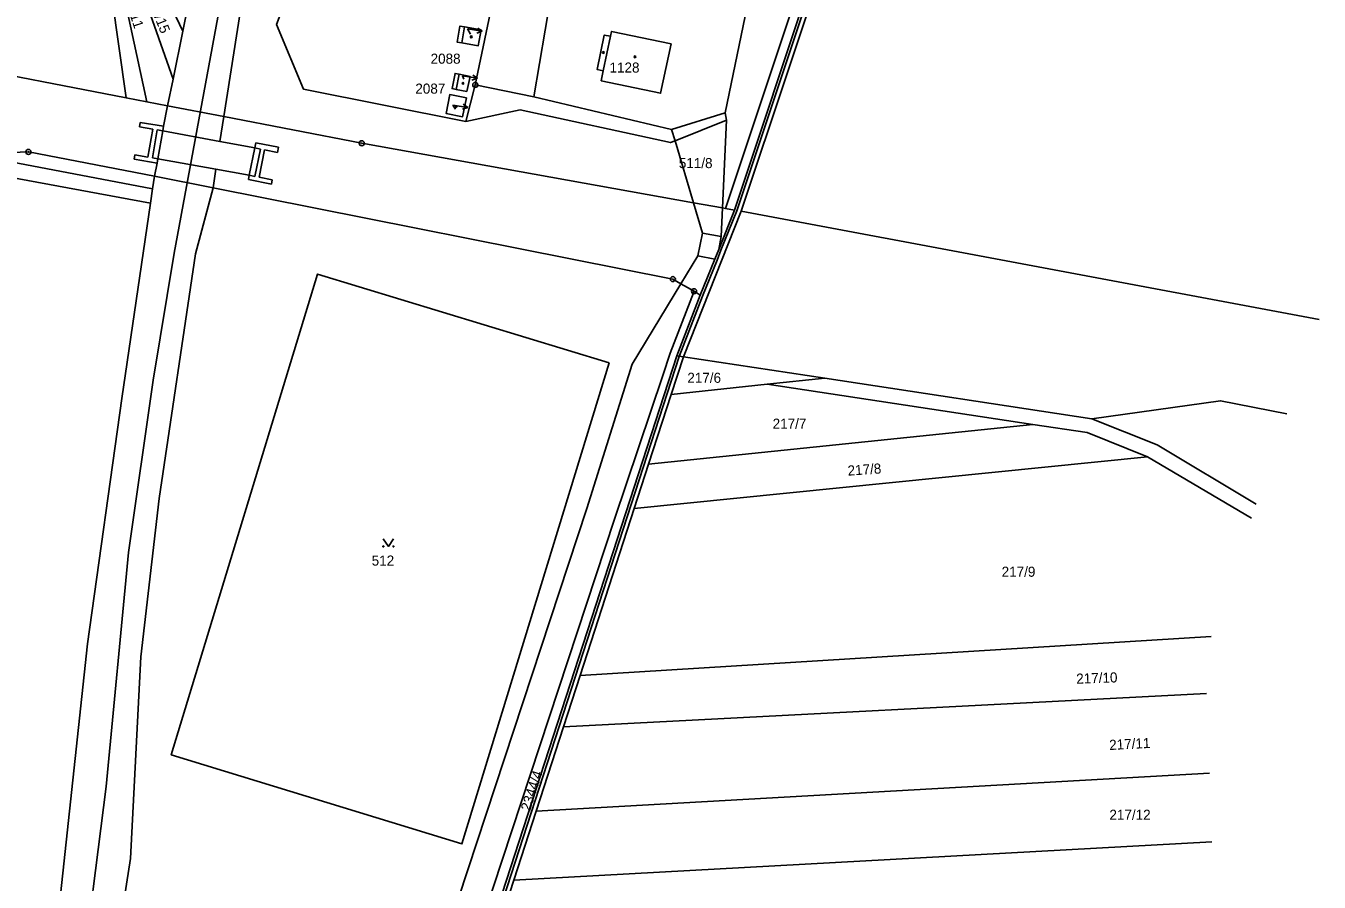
# Model space of a CAD drawing. Extents: x -555757 to -553364, y -1100723 to -1096439.
# Drawn here: x -553994.7 to -553738.1, y -1100289.4 to -1100119.7 of the extents above; entities that cross this region are included whole.
import ezdxf

# ---------------------------------------------------------------- set-up
doc = ezdxf.new("R2010")
doc.units = 0
for name, color, linetype in [('01_HLADINA', 7, 'Continuous'), ('BUDOVY', 7, 'Continuous'), ('C$SLO$PARCELY', 7, 'Continuous'), ('HRANICE$PARCELY', 7, 'Continuous'), ('HRANICE_PARCEL', 7, 'Continuous'), ('PLOTY', 7, 'Continuous'), ('SLOUPY', 7, 'Continuous'), ('SLUCKOV$$C$RA', 7, 'Continuous'), ('VSTUP', 7, 'Continuous'), ('ZNA$KY$KULTUR', 7, 'Continuous')]:
    doc.layers.add(name, color=color, linetype=linetype)

# ---------------------------------------------------------------- blocks, each defined once
blk = doc.blocks.new('4$02')
at = {"layer": 'SLOUPY'}
blk.add_circle((0, 0), 0.175, dxfattribs=at)
blk = doc.blocks.new('1029')
at = {"layer": 'PLOTY'}
for p, q in [((0, 0), (2.964, -0.468)), ((2.964, -0.468), (2.052, 0.182)), ((2.964, -0.468), (1.897, -0.807))]:
    blk.add_line(p, q, dxfattribs=at)
blk = doc.blocks.new('3$14')
at = {"layer": 'ZNA$KY$KULTUR'}
blk.add_lwpolyline([(-1, 1.5), (0, 0), (1, 1.5)], dxfattribs=at)
for centre in [(-1, 0), (1, 0)]:
    blk.add_circle(centre, 0.1, dxfattribs=at)
blk = doc.blocks.new('1$05')
at = {"layer": 'SLOUPY'}
for radius in [0.5, 0.032]:
    blk.add_circle((0, 0), radius, dxfattribs=at)

msp = doc.modelspace()

# ---------------------------------------------------------------- linework, layer by layer
at = {"layer": '01_HLADINA'}
msp.add_lwpolyline([(-553953.11, -1100099.32), (-553965.26, -1100164.74), (-553969.41, -1100189.9), (-553974.3, -1100224.07), (-553978.76, -1100270.49), (-553983.95, -1100311.58), (-553989.5, -1100329.15), (-553995.79, -1100344.5), (-554001.62, -1100365.99), (-554010.25, -1100383.72), (-554044.69, -1100426.79), (-554056.93, -1100450.05), (-554073.88, -1100483.25), (-554097.67, -1100514.34), (-554108.96, -1100533.61), (-554110.14, -1100539.01), (-554109.2, -1100543.24), (-554088.7, -1100559.12), (-554040.77, -1100604.47), (-554031.29, -1100609.85)], dxfattribs=at)
at = {"layer": 'HRANICE$PARCELY'}
for p, q in [((-553974.78, -1100133.9), (-553980.8, -1100091.31)), ((-553973.75, -1100099.21), (-553963.53, -1100120.74)), ((-553976.01, -1100110.13), (-553970.66, -1100134.7)), ((-553965.47, -1100130.22), (-553972.7, -1100109.51)), ((-553963.53, -1100120.74), (-553962.46, -1100115.49)), ((-553963.53, -1100120.74), (-553965.47, -1100130.22)), ((-553966.55, -1100135.49), (-553965.47, -1100130.22)), ((-553974.78, -1100133.9), (-553970.66, -1100134.7)), ((-553970.66, -1100134.7), (-553966.55, -1100135.49)), ((-553966.55, -1100135.49), (-553955.39, -1100137.65)), ((-553865.86, -1100142.45), (-553855.64, -1100138.34)), ((-553855.64, -1100138.34), (-553856.45, -1100155.76)), ((-553862.18, -1100154.74), (-553865.86, -1100142.45)), ((-553957.49, -1100151.77), (-553969.15, -1100149.45)), ((-553862.18, -1100154.74), (-553856.45, -1100155.76)), ((-553864.19, -1100185.27), (-553852.74, -1100156.42)), ((-553856.45, -1100155.76), (-553855.82, -1100155.88)), ((-553855.82, -1100155.88), (-553854.07, -1100156.19)), ((-553738.06, -1100177.87), (-553852.74, -1100156.42)), ((-553874.39, -1100186.73), (-553864.69, -1100170.78)), ((-553862.09, -1100172.27), (-553864.69, -1100170.78)), ((-553860.87, -1100173.08), (-553862.09, -1100172.27)), ((-553866.61, -1100192.72), (-553864.19, -1100185.27)), ((-553864.19, -1100185.27), (-553865.48, -1100185.07)), ((-553864.19, -1100185.27), (-553836.12, -1100189.52)), ((-553866.61, -1100192.72), (-553847.56, -1100190.72)), ((-553836.12, -1100189.52), (-553847.56, -1100190.72)), ((-553847.56, -1100190.72), (-553794.86, -1100198.68)), ((-553836.12, -1100189.52), (-553783.13, -1100197.54)), ((-553871.11, -1100206.59), (-553866.61, -1100192.72)), ((-553871.11, -1100206.59), (-553794.86, -1100198.68)), ((-553873.96, -1100215.36), (-553772.14, -1100205.09)), ((-553772.14, -1100205.09), (-553751.49, -1100217.26)), ((-553873.96, -1100215.36), (-553871.11, -1100206.59)), ((-553884.7, -1100248.44), (-553873.96, -1100215.36)), ((-553884.7, -1100248.44), (-553759.5, -1100240.75)), ((-553888, -1100258.61), (-553884.7, -1100248.44)), ((-553888, -1100258.61), (-553760.38, -1100252.01)), ((-553893.42, -1100275.33), (-553888, -1100258.61)), ((-553893.42, -1100275.33), (-553759.84, -1100267.83)), ((-553897.87, -1100289.02), (-553893.42, -1100275.33)), ((-553897.87, -1100289.02), (-553759.37, -1100281.41))]:
    msp.add_line(p, q, dxfattribs=at)
for points in [[(-553907.37, -1100138.61), (-553939.55, -1100132.22), (-553944.91, -1100119.39), (-553920.27, -1100053.8), (-553914.93, -1100045.6), (-553847.15, -1099965.99), (-553812.36, -1099934.8), (-553809.19, -1099892.09), (-553807.54, -1099892.27), (-553806.84, -1099889.23), (-553809.31, -1099888.44), (-553798.08, -1099842.22), (-553794.08, -1099832.41)], [(-553852.74, -1100156.42), (-553750.94, -1099851.94), (-553751.35, -1099851.71)], [(-553820.44, -1099888.78), (-553821.21, -1099891.71), (-553820.09, -1099892.13), (-553820.37, -1099892.88), (-553821.49, -1099892.46), (-553824.11, -1099899.49), (-553822.99, -1099899.91), (-553823.26, -1099900.66), (-553824.39, -1099900.24), (-553825.18, -1099904.09), (-553825.84, -1099907.27), (-553822.76, -1099907.91), (-553822.92, -1099908.7), (-553817.67, -1099909.79), (-553816.58, -1099926.52), (-553821.03, -1099933.32), (-553832.46, -1099946.01), (-553847.23, -1099954.8), (-553908.3, -1100026.68), (-553927.2, -1100052.65), (-553950.17, -1100104.31), (-553955.39, -1100137.65)], [(-553827.74, -1100062.31), (-553830.25, -1100061.66), (-553887.72, -1100046.78), (-553905.49, -1100131.36), (-553907.37, -1100138.61)], [(-553855.82, -1100155.88), (-553824.86, -1100063.06), (-553825.46, -1100062.9)], [(-554085.02, -1100114.21), (-554082.54, -1100114.55), (-554010.35, -1100127.02), (-553974.78, -1100133.9)], [(-553904.36, -1100120.43), (-553907.61, -1100119.87), (-553908.55, -1100119.71), (-553909.1, -1100122.86), (-553908.16, -1100123.02), (-553904.91, -1100123.59), (-553904.36, -1100120.43)], [(-553878.66, -1100121.73), (-553879.9, -1100121.47), (-553881.31, -1100128.33), (-553880.09, -1100128.58), (-553880.5, -1100130.54), (-553868.73, -1100133.02), (-553866.66, -1100123.24), (-553878.45, -1100120.76), (-553878.66, -1100121.73)], [(-553907.14, -1100132.67), (-553906.54, -1100129.68), (-553908.7, -1100129.25), (-553909.5, -1100129.09), (-553910.09, -1100132.09), (-553909.3, -1100132.24), (-553907.14, -1100132.67)], [(-553907.27, -1100133.93), (-553910.55, -1100133.28), (-553911.3, -1100137.03), (-553908.01, -1100137.68), (-553907.27, -1100133.93)], [(-553865.86, -1100142.45), (-553866.76, -1100142.81), (-553896.58, -1100136.32), (-553907.37, -1100138.61)], [(-553955.39, -1100137.65), (-553928.03, -1100142.94), (-553862.18, -1100154.74)], [(-553969.15, -1100149.45), (-553994.16, -1100144.65), (-554005.7, -1100145.07), (-554026.82, -1100141.05)], [(-553975.6, -1100193.57), (-553969.94, -1100154.83), (-553969.52, -1100151.97), (-553969.15, -1100149.45)], [(-553957.49, -1100151.77), (-553961.04, -1100164.84), (-553968.24, -1100213.36), (-553971.85, -1100244.73), (-553973.89, -1100284.73), (-553980.03, -1100324.22), (-553990.03, -1100341.67), (-553995.55, -1100364.16), (-554005.15, -1100386.96), (-554032.98, -1100417.03), (-554047.76, -1100443)], [(-553864.69, -1100170.78), (-553866.29, -1100169.87), (-553957.49, -1100151.77)], [(-553878.94, -1100186.47), (-553908.16, -1100281.84), (-553965.81, -1100264.16), (-553936.78, -1100168.87), (-553878.94, -1100186.47)], [(-553868.31, -1100189), (-553866.84, -1100184.54), (-553862.09, -1100172.27)], [(-553936.03, -1100360.91), (-553925.98, -1100343.56), (-553919.7, -1100325.51), (-553883.36, -1100215.37), (-553874.39, -1100186.73)], [(-553903.81, -1100296.11), (-553877.84, -1100217.43), (-553868.31, -1100189)], [(-553990.26, -1100314.68), (-553982.45, -1100242.15), (-553975.6, -1100193.57)], [(-553783.13, -1100197.54), (-553757.61, -1100194), (-553744.44, -1100196.6)], [(-553794.86, -1100198.68), (-553784.06, -1100200.31), (-553772.14, -1100205.09)], [(-553750.55, -1100214.5), (-553770.17, -1100202.71), (-553783.13, -1100197.54)], [(-553899.62, -1100305.56), (-553899.53, -1100303.59), (-553900.98, -1100298.61), (-553897.87, -1100289.02)]]:
    msp.add_lwpolyline(points, dxfattribs=at)
at = {"layer": 'HRANICE_PARCEL'}
msp.add_line((-553860.87, -1100173.08), (-553865.48, -1100185.07), dxfattribs=at)
msp.add_line((-553860.87, -1100173.08), (-553865.48, -1100185.07), dxfattribs=at)
for points in [[(-553772.42, -1099910.5), (-553808.14, -1100018.35), (-553854.07, -1100156.19)], [(-553772.42, -1099910.5), (-553808.14, -1100018.35), (-553854.07, -1100156.19)], [(-553854.07, -1100156.19), (-553857.2, -1100163.97), (-553857.97, -1100165.89), (-553860.87, -1100173.08)], [(-553854.07, -1100156.19), (-553857.2, -1100163.97), (-553857.97, -1100165.89), (-553860.87, -1100173.08)], [(-553865.48, -1100185.07), (-553901.86, -1100296.95), (-553904.98, -1100335.31), (-553898.6, -1100364.02), (-553903.77, -1100393.32)], [(-553865.48, -1100185.07), (-553901.86, -1100296.95), (-553904.98, -1100335.31), (-553898.6, -1100364.02), (-553903.77, -1100393.32)]]:
    msp.add_lwpolyline(points, dxfattribs=at)
at = {"layer": 'PLOTY'}
for p, q in [((-553906.45, -1100121.3), (-553907.07, -1100120.27)), ((-553907.75, -1100130.22), (-553908.05, -1100129.59)), ((-553909.43, -1100136.16), (-553909.96, -1100135.37))]:
    msp.add_line(p, q, dxfattribs=at)
at = {"layer": 'SLUCKOV$$C$RA'}
for p, q in [((-553807.67, -1100018.51), (-553853.6, -1100156.36)), ((-553881.2, -1100059.22), (-553893.89, -1100133.71)), ((-553855.92, -1100136.88), (-553841.85, -1100069.34)), ((-553908.16, -1100123.02), (-553907.61, -1100119.87)), ((-553880.09, -1100128.58), (-553878.66, -1100121.73)), ((-553909.3, -1100132.24), (-553908.7, -1100129.25)), ((-553905.49, -1100131.36), (-553893.89, -1100133.71)), ((-553893.89, -1100133.71), (-553866.54, -1100140.2)), ((-553967.39, -1100139.57), (-553966.55, -1100135.49)), ((-553866.54, -1100140.2), (-553855.92, -1100136.88)), ((-553855.64, -1100138.34), (-553855.92, -1100136.88)), ((-553971.96, -1100138.8), (-553972.11, -1100139.68)), ((-553972.11, -1100139.68), (-553969.48, -1100140.15)), ((-553967.39, -1100139.57), (-553971.96, -1100138.8)), ((-553967.5, -1100140.5), (-553967.39, -1100139.57)), ((-553956.16, -1100142.58), (-553955.39, -1100137.65)), ((-553969.48, -1100140.15), (-553970.44, -1100145.66)), ((-553969.56, -1100145.81), (-553968.59, -1100140.3)), ((-553968.59, -1100140.3), (-553967.5, -1100140.5)), ((-553967.5, -1100140.5), (-553968.47, -1100146)), ((-553956.16, -1100142.58), (-553967.5, -1100140.5)), ((-553866.54, -1100140.2), (-553865.86, -1100142.45)), ((-553969.94, -1100154.83), (-554026.21, -1100144.48)), ((-553949.27, -1100143.85), (-553956.16, -1100142.58)), ((-553950.34, -1100149.29), (-553949.27, -1100143.85)), ((-553949.07, -1100142.82), (-553949.27, -1100143.85)), ((-553949.27, -1100143.85), (-553948.14, -1100144.07)), ((-553948.14, -1100144.07), (-553949.21, -1100149.51)), ((-553944.51, -1100143.71), (-553949.07, -1100142.82)), ((-553948.38, -1100149.67), (-553947.31, -1100144.23)), ((-553947.31, -1100144.23), (-553944.71, -1100144.74)), ((-553944.71, -1100144.74), (-553944.51, -1100143.71)), ((-553969.52, -1100151.97), (-554005.7, -1100145.07)), ((-553973.2, -1100146.1), (-553973.05, -1100145.21)), ((-553968.63, -1100146.88), (-553973.2, -1100146.1)), ((-553973.05, -1100145.21), (-553970.44, -1100145.66)), ((-553969.56, -1100145.81), (-553968.47, -1100146)), ((-553969.15, -1100149.45), (-553968.63, -1100146.88)), ((-553968.47, -1100146), (-553968.63, -1100146.88)), ((-553968.47, -1100146), (-553956.96, -1100148.09)), ((-553957.49, -1100151.77), (-553956.96, -1100148.09)), ((-553956.96, -1100148.09), (-553950.34, -1100149.29)), ((-553950.34, -1100149.29), (-553950.5, -1100150.13)), ((-553949.21, -1100149.51), (-553950.34, -1100149.29)), ((-553945.78, -1100150.18), (-553948.38, -1100149.67)), ((-553950.5, -1100150.13), (-553945.94, -1100151.02)), ((-553945.94, -1100151.02), (-553945.78, -1100150.18)), ((-553860.38, -1100160.76), (-553862.18, -1100154.74)), ((-553853.6, -1100156.36), (-553856.74, -1100164.16)), ((-553856.71, -1100161.44), (-553856.45, -1100155.76)), ((-553861.33, -1100165.26), (-553860.38, -1100160.76)), ((-553860.38, -1100160.76), (-553856.71, -1100161.44)), ((-553857.2, -1100163.97), (-553856.71, -1100161.44)), ((-553864.69, -1100170.78), (-553861.33, -1100165.26)), ((-553861.33, -1100165.26), (-553857.97, -1100165.89)), ((-553856.74, -1100164.16), (-553857.51, -1100166.08)), ((-553857.51, -1100166.08), (-553860.4, -1100173.26)), ((-553860.4, -1100173.26), (-553865.01, -1100185.24)), ((-553865.01, -1100185.24), (-553901.37, -1100297.05))]:
    msp.add_line(p, q, dxfattribs=at)

# ---------------------------------------------------------------- block references
at = {"layer": 'BUDOVY'}
for p in [(-553906.3, -1100121.84), (-553880.09, -1100124.93), (-553873.8, -1100125.79), (-553907.94, -1100131.05), (-553909.32, -1100135.62)]:
    msp.add_blockref('4$02', p, dxfattribs=at)
at = {"layer": 'PLOTY'}
for p in [(-553907.07, -1100120.27), (-553908.05, -1100129.59), (-553909.96, -1100135.37)]:
    msp.add_blockref('1029', p, dxfattribs=at)
at = {"layer": 'VSTUP'}
for p in [(-553905.49, -1100131.36), (-553994.16, -1100144.65), (-553928.03, -1100142.94), (-553866.29, -1100169.87), (-553862.09, -1100172.27)]:
    msp.add_blockref('1$05', p, dxfattribs=at)
at = {"layer": 'ZNA$KY$KULTUR'}
msp.add_blockref('3$14', (-553922.74, -1100222.86), dxfattribs=at)

# ---------------------------------------------------------------- texts
at = {"layer": 'C$SLO$PARCELY'}
for s, rotation, p in [('517/11', 288, (-553975.65, -1100112.57)), ('517/15', 292, (-553970.89, -1100113.76)), ('217/8', 4, (-553831.55, -1100208.85)), ('217/10', 2, (-553786.22, -1100250.1)), ('217/11', 3, (-553779.66, -1100263.24)), ('2344/4', 72, (-553894.64, -1100275.49))]:
    msp.add_text(s, height=2, rotation=rotation, dxfattribs=at).set_placement(p)
for s, p in [('2088', (-553914.36, -1100127.16)), ('1128', (-553878.86, -1100128.92)), ('2087', (-553917.39, -1100133.1)), ('511/8', (-553865.11, -1100147.86)), ('217/6', (-553863.42, -1100190.43)), ('217/7', (-553846.49, -1100199.53)), ('512', (-553926.05, -1100226.67)), ('217/9', (-553801.05, -1100228.88)), ('217/12', (-553779.67, -1100277.07))]:
    msp.add_text(s, height=2, dxfattribs=at).set_placement(p)

doc.saveas('drawing.dxf')
